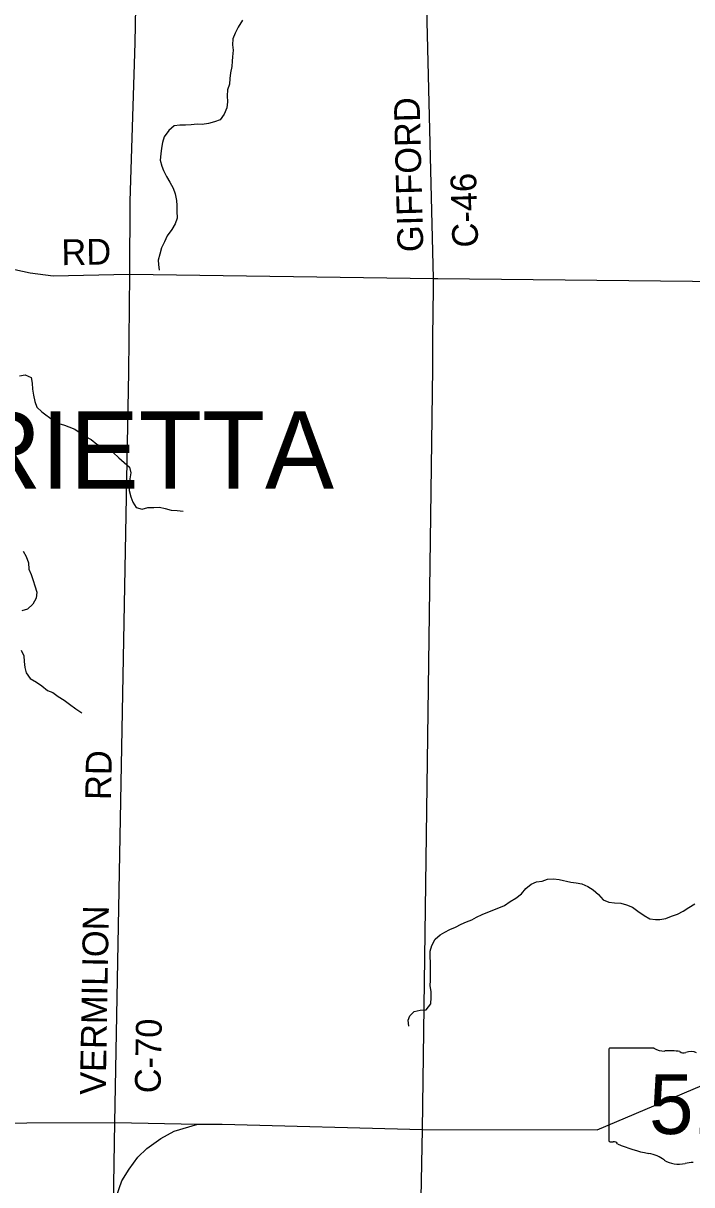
# Model space of a CAD drawing. Extents: x 1857828 to 2277390, y 930619 to 1324581.
# Drawn here: x 2022049 to 2029836, y 1196864 to 1210395 of the extents above; entities that cross this region are included whole.
import ezdxf

# ---------------------------------------------------------------- set-up
doc = ezdxf.new("R2010")
doc.units = 0
for name, color, linetype in [('GM_X_County_Road', 7, 'Continuous'), ('GM_X_County_Road_Text', 7, 'Continuous'), ('GM_X_Minor_River', 7, 'Continuous'), ('GM_X_State_Location', 7, 'Continuous'), ('GM_X_State_Route', 7, 'Continuous'), ('GM_X_State_Shield', 7, 'Continuous'), ('GM_X_Township_Road', 7, 'Continuous'), ('GM_X_Township_Road_Text', 7, 'Continuous'), ('GM_X_Township_Text', 7, 'Continuous')]:
    doc.layers.add(name, color=color, linetype=linetype)

msp = doc.modelspace()

# ---------------------------------------------------------------- linework, layer by layer
at = {"layer": 'GM_X_County_Road'}
for points in [[(2026826, 1207423), (2026650, 1214675), (2026641, 1214919), (2026637, 1215040), (2026631, 1215134), (2026621, 1215259), (2026616, 1215333), (2026612, 1215409), (2026608, 1215491), (2026608, 1215578), (2026608, 1215640), (2026610, 1215708), (2026611, 1215772), (2026603, 1216021), (2026517, 1218397)], [(2023292, 1207473), (2023295, 1208322), (2023354, 1210168), (2023387, 1212040), (2023442, 1213651), (2023461, 1214644), (2023461, 1215754), (2023450, 1217251), (2023441, 1217534)], [(2023117, 1197590), (2023277, 1206329), (2023292, 1207473)], [(2015362, 1197576), (2019013, 1197572), (2023117, 1197590)], [(2023101, 1196630), (2023117, 1197590)], [(2023117, 1197590), (2024084, 1197571)]]:
    msp.add_lwpolyline(points, dxfattribs=at)
at = {"layer": 'GM_X_Minor_River'}
for points in [[(2024603, 1210430), (2024554, 1210350), (2024519, 1210280), (2024492, 1210214), (2024487, 1210144), (2024493, 1210082), (2024486, 1210004), (2024483, 1209954), (2024478, 1209892), (2024463, 1209819), (2024457, 1209751), (2024450, 1209687), (2024429, 1209619), (2024424, 1209549), (2024429, 1209481), (2024420, 1209411), (2024389, 1209335), (2024342, 1209269), (2024278, 1209246), (2024205, 1209229), (2024133, 1209217), (2024073, 1209218), (2024004, 1209211), (2023938, 1209206), (2023872, 1209208), (2023805, 1209201), (2023746, 1209146), (2023691, 1209072), (2023670, 1209006), (2023660, 1208938), (2023651, 1208874), (2023644, 1208800), (2023665, 1208731), (2023681, 1208681), (2023716, 1208610), (2023757, 1208542), (2023797, 1208475), (2023818, 1208407), (2023833, 1208330), (2023838, 1208270), (2023838, 1208204), (2023841, 1208123), (2023818, 1208059), (2023779, 1207994), (2023724, 1207920), (2023693, 1207848), (2023658, 1207778), (2023639, 1207706), (2023620, 1207636), (2023624, 1207586), (2023633, 1207518)], [(2022007, 1206289), (2022071, 1206300), (2022140, 1206270), (2022153, 1206202), (2022157, 1206134), (2022168, 1206062), (2022183, 1205990), (2022206, 1205922), (2022267, 1205867), (2022401, 1205768), (2022463, 1205732), (2022528, 1205711), (2022580, 1205692), (2022649, 1205666), (2022774, 1205580), (2022841, 1205546), (2022908, 1205491), (2022968, 1205459), (2023031, 1205424), (2023096, 1205393), (2023163, 1205333), (2023226, 1205278), (2023288, 1205224), (2023301, 1205156), (2023290, 1205086), (2023285, 1205012), (2023283, 1204953), (2023302, 1204879), (2023325, 1204815), (2023366, 1204754), (2023433, 1204736), (2023499, 1204753), (2023571, 1204754), (2023637, 1204757), (2023702, 1204742), (2023772, 1204724), (2023840, 1204717), (2023913, 1204712)], [(2022048, 1204243), (2022083, 1204183), (2022112, 1204109), (2022115, 1204037), (2022142, 1203975), (2022165, 1203905), (2022185, 1203841), (2022208, 1203769), (2022201, 1203697), (2022160, 1203628), (2022100, 1203571), (2022032, 1203549)], [(2022025, 1203091), (2022054, 1203027), (2022061, 1202959), (2022066, 1202891), (2022084, 1202827), (2022131, 1202761), (2022202, 1202718), (2022265, 1202676), (2022330, 1202621), (2022392, 1202598), (2022457, 1202550), (2022524, 1202509), (2022589, 1202464), (2022660, 1202408), (2022732, 1202363)], [(2026539, 1198713), (2026534, 1198781), (2026550, 1198833), (2026603, 1198883), (2026674, 1198896), (2026742, 1198901), (2026795, 1198973), (2026802, 1199045), (2026799, 1199115), (2026789, 1199182), (2026794, 1199246), (2026793, 1199318), (2026792, 1199388), (2026791, 1199454), (2026789, 1199519), (2026790, 1199587), (2026807, 1199651), (2026846, 1199723), (2026907, 1199774), (2026958, 1199806), (2027018, 1199837), (2027083, 1199864), (2027149, 1199898), (2027212, 1199927), (2027273, 1199950), (2027329, 1199982), (2027394, 1200011), (2027519, 1200062), (2027588, 1200089), (2027656, 1200118), (2027721, 1200162), (2027786, 1200203), (2027851, 1200253), (2027902, 1200314), (2027966, 1200364), (2028029, 1200391), (2028093, 1200402), (2028156, 1200422), (2028224, 1200427), (2028290, 1200420), (2028427, 1200390), (2028491, 1200381), (2028557, 1200371), (2028625, 1200340), (2028687, 1200299), (2028750, 1200244), (2028802, 1200185), (2028870, 1200156), (2028936, 1200149), (2029010, 1200143), (2029074, 1200126), (2029144, 1200097), (2029208, 1200052), (2029280, 1200001), (2029346, 1199960), (2029414, 1199955), (2029464, 1199955), (2029532, 1199966), (2029601, 1199991), (2029668, 1200016), (2029734, 1200050), (2029803, 1200093), (2029870, 1200138)]]:
    msp.add_lwpolyline(points, dxfattribs=at)
at = {"layer": 'GM_X_State_Route'}
for points in [[(2024189, 1197570), (2024365, 1197569), (2026699, 1197509), (2028734, 1197505), (2030511, 1198257), (2032474, 1199137), (2034866, 1200209), (2038668, 1200196)], [(2022944, 1191744), (2022995, 1192731), (2023011, 1193448), (2023072, 1196160), (2023101, 1196630), (2023196, 1196911), (2023281, 1197047), (2023384, 1197187), (2023490, 1197286), (2023652, 1197404), (2023806, 1197488), (2024084, 1197571), (2024189, 1197570)]]:
    msp.add_lwpolyline(points, dxfattribs=at)
at = {"layer": 'GM_X_State_Shield'}
for p, q in [((2028869, 1198438), (2028869, 1197381)), ((2029396, 1198456), (2028886, 1198456))]:
    msp.add_line(p, q, dxfattribs=at)
for centre, major_axis, start_param, end_param in [((2028889, 1198440), (20.2, 0), 1.712693, 3.28349), ((2029517, 1198578), (196, 0), 4.042523, 4.731795), ((2029582, 1197863), (702, 0), 1.404758, 1.657858), ((2029741, 1198445), (56.4, 0), 3.836095, 5.185415), ((2029824, 1198323), (117, 0), 0.950623, 2.079405), ((2028889, 1197379), (20.3, 0), 3.00124, 4.508301), ((2028892, 1197487), (155, 0), 4.665946, 4.897461), ((2028924, 1197320), (56, 0), 0.519207, 1.627899), ((2029630, 1198269), (1333, 0), 4.195997, 4.488961), ((2029233, 1196906), (417, 0), 0.823519, 1.323587), ((2029684, 1197315), (265, 0), 4.026481, 4.996735), ((2029837, 1196949), (217, 0), 1.495662, 1.94098)]:
    msp.add_ellipse(centre, major_axis=major_axis, ratio=0.8, start_param=start_param, end_param=end_param, dxfattribs=at)
at = {"layer": 'GM_X_Township_Road'}
for points in [[(2018821, 1207743), (2020969, 1207739), (2022128, 1207489), (2022399, 1207453), (2023284, 1207472)], [(2023284, 1207472), (2023292, 1207473), (2026826, 1207423), (2026877, 1207422)], [(2026818, 1206379), (2026819, 1206494), (2026820, 1206721), (2026825, 1207038), (2026827, 1207291), (2026826, 1207423)], [(2026877, 1207422), (2030955, 1207378)], [(2026699, 1197509), (2026818, 1206374), (2026818, 1206379)], [(2026604, 1193389), (2026607, 1193454), (2026614, 1193649), (2026633, 1194126), (2026699, 1197509)]]:
    msp.add_lwpolyline(points, dxfattribs=at)

# ---------------------------------------------------------------- texts
at = {"layer": 'GM_X_County_Road_Text'}
for s, rotation, p in [('GIFFORD', 91.444, (2026710, 1207732)), ('C-46', 91.7153, (2027349, 1207786)), ('RD', 89.0128, (2023071, 1201344)), ('VERMILION', 89.0207, (2023009, 1197908)), ('C-70', 88.9714, (2023648, 1197927))]:
    msp.add_text(s, height=300, rotation=rotation, dxfattribs=at).set_placement(p)
at = {"layer": 'GM_X_State_Location'}
for s in ['s', 'r']:
    msp.add_text(s, height=1, dxfattribs=at).set_placement((2029719, 1197839))
msp.add_text('511', height=1, rotation=0, dxfattribs=at).set_placement((2029366, 1197766))
at = {"layer": 'GM_X_State_Shield'}
msp.add_text('511', height=696.1, dxfattribs=at).set_placement((2029338, 1197455))
at = {"layer": 'GM_X_Township_Road_Text'}
msp.add_text('RD', height=300, rotation=0.9872, dxfattribs=at).set_placement((2022496, 1207576))
at = {"layer": 'GM_X_Township_Text'}
msp.add_text('HENRIETTA', height=900, rotation=0, dxfattribs=at).set_placement((2018848, 1204974))

doc.saveas('drawing.dxf')
